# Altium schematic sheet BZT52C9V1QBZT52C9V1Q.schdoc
size 127 x 101 mm
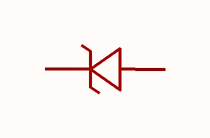
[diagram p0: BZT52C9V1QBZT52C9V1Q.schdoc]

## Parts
D?  bzt52c9v1q  [SOD-123_L2.7-W1.6-LS3.8-RD]  (value not drawn)

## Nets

Not connected (* = marked no-connect by the designer): D? 1(K) 2(A)

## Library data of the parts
D? = bzt52c9v1q: 二极管配置:1个独立式;稳压值(标称值):9.1V;稳压值(范围值):8.65V~9.56V;耗散功率(Pd):500mW;; Manufacturer: JSMSEMI(杰盛微); AddInBom: yes; ModelId: 08ed98efebd24e50a5f1756366a20a49; ModelTransform: 147.6375,62.992,0,0,0,0,0,0,0; Diode Configuration: 1个独立式; Zener Voltage(Nom): 9.1V; Reverse Leakage Current (Ir): 500nA@6V; Pd - Power Dissipation: 500mW; Impedance(Zzt): 15Ω; Impedance(Zzk): 100Ω; Operating Junction Temperature Range: -55℃~+150℃; Tolerance: ±5%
